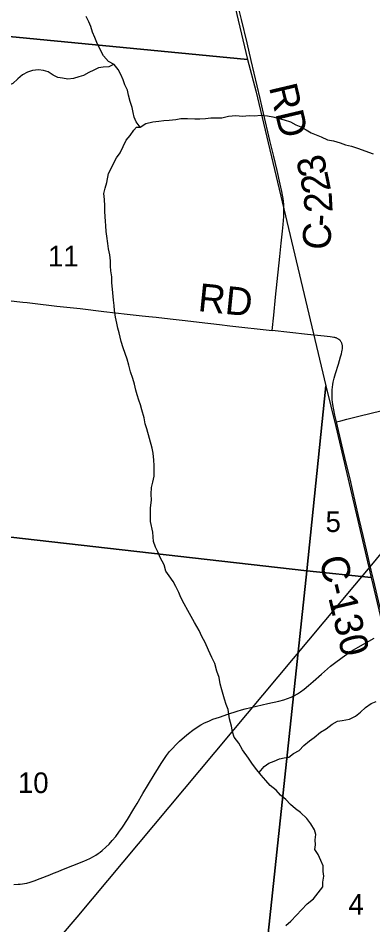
# Model space of a CAD drawing. Extents: x 0 to 1101, y 0 to 440.
# Drawn here: x 843.45 to 844.169, y 371.828 to 373.668 of the extents above; entities that cross this region are included whole.
import ezdxf

# ---------------------------------------------------------------- set-up
doc = ezdxf.new("R2010")
doc.units = 0
for name, color, linetype in [('GM_X_County_Road', 7, 'Continuous'), ('GM_X_County_Road_Text', 7, 'Continuous'), ('GM_X_Minor_River', 7, 'Continuous'), ('GM_X_Rail_Line', 7, 'Continuous'), ('GM_X_Section', 7, 'Continuous'), ('GM_X_Section_Text', 7, 'Continuous'), ('GM_X_Township_Road', 7, 'Continuous'), ('GM_X_Township_Road_Text', 7, 'Continuous')]:
    doc.layers.add(name, color=color, linetype=linetype)

msp = doc.modelspace()

# ---------------------------------------------------------------- linework, layer by layer
at = {"layer": 'GM_X_County_Road'}
for points in [[(843.9652, 373.0339), (843.9682, 373.0647), (843.9719, 373.1013), (843.9752, 373.1334), (843.9802, 373.1841), (843.9832, 373.2113), (843.986, 373.2354), (843.9873, 373.249), (843.9886, 373.2651), (843.9889, 373.2776), (843.9887, 373.2843), (843.9885, 373.2895), (843.9879, 373.2956), (843.9871, 373.3019), (843.9861, 373.3083), (843.9846, 373.316), (843.9815, 373.3306), (843.975, 373.3584), (843.9682, 373.3868), (843.9604, 373.4195), (843.9475, 373.4745), (843.9406, 373.5042), (843.9223, 373.5815), (843.914, 373.6172), (843.9028, 373.6649), (843.891, 373.7144)], [(844.0951, 372.8485), (844.092, 372.8618), (844.0898, 372.8727), (844.0879, 372.8837), (844.0874, 372.8887), (844.0868, 372.8941), (844.0865, 372.9015), (844.0865, 372.9083), (844.0868, 372.9136), (844.0872, 372.9188), (844.088, 372.9243), (844.0889, 372.9291), (844.0907, 372.9369), (844.0933, 372.9465), (844.0992, 372.9655), (844.1037, 372.9804), (844.1053, 372.9864), (844.1062, 372.9906), (844.1068, 372.9938), (844.1072, 372.9964), (844.1073, 372.9985), (844.1074, 373.0003), (844.1073, 373.0021), (844.1072, 373.0036), (844.1071, 373.0048), (844.1068, 373.0059), (844.1064, 373.0072), (844.106, 373.0084), (844.1055, 373.0096), (844.105, 373.0105), (844.1043, 373.0116), (844.1037, 373.0126), (844.103, 373.0133), (844.1021, 373.0142), (844.1003, 373.0158), (844.0992, 373.0165), (844.0981, 373.0172), (844.0969, 373.0179), (844.0957, 373.0184), (844.0944, 373.0188), (844.0932, 373.0192), (844.0917, 373.0195), (844.0901, 373.0199), (844.0866, 373.0205), (844.0826, 373.0211), (844.0766, 373.0219), (844.0705, 373.0226), (844.0364, 373.026), (843.9652, 373.0339)], [(844.0951, 372.8485), (844.1043, 372.8508), (844.1163, 372.8539), (844.1435, 372.8605), (844.1852, 372.8706), (844.2117, 372.877), (844.2969, 372.8975), (844.3435, 372.9084), (844.3956, 372.9205), (844.4379, 372.9305), (844.4724, 372.9384), (844.4991, 372.9444), (844.5323, 372.9523), (844.5711, 372.9613), (844.6182, 372.9725), (844.6593, 372.9823), (844.7029, 372.9924), (844.7146, 372.9951)], [(844.1957, 372.4215), (844.1896, 372.4469), (844.1823, 372.4766), (844.1707, 372.5261), (844.1657, 372.5478), (844.1583, 372.5799), (844.1493, 372.618), (844.1415, 372.6519), (844.1339, 372.6846), (844.1278, 372.7113), (844.1227, 372.733), (844.1148, 372.765), (844.1061, 372.8019), (844.0951, 372.8485)], [(843.4417, 371.9103), (843.4505, 371.9104), (843.4545, 371.9107), (843.4592, 371.9112), (843.4633, 371.9118), (843.4679, 371.9128), (843.4745, 371.9146), (843.4828, 371.9173), (843.4951, 371.9219), (843.5142, 371.9295), (843.5221, 371.9328), (843.5314, 371.9366), (843.5388, 371.9397), (843.5832, 371.9575), (843.5953, 371.9626), (843.6032, 371.9665), (843.6079, 371.9695), (843.6126, 371.9727), (843.6167, 371.9759), (843.6204, 371.9789), (843.6279, 371.9855), (843.6345, 371.9921), (843.6408, 371.9991), (843.648, 372.0077), (843.6544, 372.0162), (843.6615, 372.0264), (843.6716, 372.0421), (843.6845, 372.0633), (843.6911, 372.0746), (843.7031, 372.0949), (843.7256, 372.1328), (843.7346, 372.147), (843.7399, 372.1554), (843.7453, 372.1637), (843.751, 372.1718), (843.7571, 372.1796), (843.7627, 372.1862), (843.7695, 372.1934), (843.7775, 372.2011), (843.7873, 372.2097), (843.7954, 372.2164), (843.8043, 372.2231), (843.8129, 372.2292), (843.8203, 372.2337), (843.8279, 372.2377), (843.8363, 372.2416), (843.8449, 372.2451), (843.8583, 372.2498), (843.8754, 372.2556), (843.8942, 372.2619), (843.9031, 372.2645), (843.9103, 372.2665), (843.9218, 372.2693), (843.9563, 372.2769), (843.9782, 372.2819), (843.9884, 372.2846), (843.9961, 372.2871), (844.0037, 372.2902), (844.0104, 372.2935), (844.0164, 372.2969), (844.0222, 372.3007), (844.0297, 372.3063), (844.0384, 372.3134), (844.0482, 372.322), (844.065, 372.3367), (844.0832, 372.3526), (844.0914, 372.3591), (844.1068, 372.3707), (844.1164, 372.3775), (844.1252, 372.3833), (844.1391, 372.3913), (844.1716, 372.4095)]]:
    msp.add_lwpolyline(points, dxfattribs=at)
at = {"layer": 'GM_X_Minor_River'}
for points in [[(843.6978, 373.4464), (843.6892, 373.4571), (843.6851, 373.4666), (843.6833, 373.4761), (843.6811, 373.4864), (843.6774, 373.4985), (843.6737, 373.5115), (843.6719, 373.5214), (843.6666, 373.532), (843.6629, 373.5423), (843.6581, 373.5534), (843.6532, 373.5633), (843.6446, 373.5732), (843.6336, 373.5794), (843.6234, 373.5909), (843.617, 373.6027), (843.6096, 373.6183), (843.6059, 373.6286), (843.6006, 373.6389), (843.5977, 373.6507), (843.5932, 373.6602), (843.588, 373.6709)], [(843.6435, 373.5738), (843.6339, 373.5688), (843.6228, 373.5681), (843.6133, 373.567), (843.6037, 373.5622), (843.5938, 373.557), (843.5827, 373.5514), (843.5731, 373.5484), (843.5625, 373.5451), (843.5506, 373.5437), (843.54, 373.5457), (843.5305, 373.5469), (843.521, 373.5519), (843.5112, 373.5584), (843.5013, 373.5612), (843.4914, 373.5628), (843.4792, 373.5614), (843.4689, 373.5581), (843.459, 373.5528), (843.4494, 373.5442), (843.4394, 373.5352), (843.4298, 373.5311), (843.4211, 373.5285)], [(843.633, 373.3521), (843.6396, 373.3638), (843.6442, 373.3743), (843.6493, 373.3842), (843.657, 373.3943), (843.6628, 373.4072), (843.669, 373.42), (843.6771, 373.4298), (843.6844, 373.4404), (843.69, 373.4466), (843.6978, 373.4464), (843.7093, 373.4538), (843.7231, 373.4571), (843.7356, 373.4585), (843.7455, 373.4596), (843.7562, 373.4606), (843.7695, 373.462), (843.7802, 373.4638), (843.7932, 373.4637), (843.808, 373.4636), (843.8183, 373.4635), (843.8297, 373.4638), (843.8404, 373.4652), (843.8632, 373.4654), (843.8762, 373.4687), (843.8911, 373.4701), (843.9048, 373.4688), (843.9181, 373.4698), (843.9291, 373.4697), (843.9421, 373.4708), (843.9558, 373.4691), (843.9664, 373.4671), (843.9763, 373.4647), (843.9896, 373.4612), (844.0021, 373.4569), (844.0131, 373.4511), (844.023, 373.4472), (844.0336, 373.4407), (844.0442, 373.4349), (844.0544, 373.431), (844.0643, 373.4271), (844.0772, 373.4206), (844.0893, 373.4189), (844.103, 373.4146), (844.1136, 373.4107), (844.1254, 373.4076), (844.1398, 373.4033), (844.1527, 373.3986), (844.1694, 373.3924)], [(844.0022, 372.0723), (843.9924, 372.0827), (843.9819, 372.0911), (843.9732, 372.1011), (843.9611, 372.1107), (843.9524, 372.1207), (843.943, 372.1318), (843.9336, 372.1425), (843.9253, 372.154), (843.9171, 372.1666), (843.9047, 372.1835), (843.8972, 372.1969), (843.8881, 372.2087), (843.8844, 372.2194), (843.8823, 372.2312), (843.8786, 372.2464), (843.8757, 372.2647), (843.8716, 372.2754), (843.8683, 372.286), (843.8627, 372.3047), (843.8598, 372.3169), (843.8573, 372.3298), (843.8528, 372.3428), (843.8488, 372.3584), (843.8428, 372.3702), (843.8361, 372.3851), (843.8294, 372.4011), (843.8226, 372.4134), (843.817, 372.4256), (843.8077, 372.4416), (843.8005, 372.4534), (843.7942, 372.466), (843.7867, 372.4794), (843.78, 372.492), (843.7759, 372.5023), (843.7699, 372.5145), (843.7646, 372.5244), (843.7564, 372.5359), (843.7496, 372.5458), (843.7463, 372.5584), (843.7381, 372.5736), (843.7336, 372.5847), (843.7287, 372.5946), (843.7243, 372.606), (843.7229, 372.6247), (843.7182, 372.6463), (843.7181, 372.674), (843.7205, 372.69), (843.7198, 372.7017), (843.7203, 372.7154), (843.7231, 372.7264), (843.7259, 372.7381), (843.726, 372.7483), (843.7257, 372.7601), (843.7254, 372.7711), (843.724, 372.7848), (843.7215, 372.7951), (843.7112, 372.8346), (843.7075, 372.8445), (843.7053, 372.8567), (843.7009, 372.873), (843.6979, 372.8829), (843.6946, 372.8928), (843.6916, 372.9035), (843.6887, 372.913), (843.6857, 372.9248), (843.6824, 372.9362), (843.678, 372.9503), (843.6743, 372.9636), (843.6714, 372.9754), (843.6669, 372.9872), (843.6632, 372.999), (843.6591, 373.0115), (843.6551, 373.0294), (843.6525, 373.0389), (843.6503, 373.0488), (843.6474, 373.0609), (843.6456, 373.0742), (843.645, 373.0845), (843.6435, 373.0955), (843.6415, 373.1175), (843.6404, 373.1304), (843.6402, 373.1426), (843.638, 373.1551), (843.6373, 373.1646), (843.6371, 373.1752), (843.636, 373.1877), (843.6335, 373.1995), (843.6321, 373.2105), (843.6299, 373.225), (843.6285, 373.2345), (843.6278, 373.2459), (843.6275, 373.2554), (843.6268, 373.2648), (843.6262, 373.2762), (843.6259, 373.2865), (843.6253, 373.2994), (843.6242, 373.3119), (843.6266, 373.3225), (843.6298, 373.3343), (843.633, 373.3521)], [(843.9385, 372.137), (843.9485, 372.1492), (843.9581, 372.156), (843.9688, 372.16), (843.9795, 372.1649), (843.9894, 372.1671), (843.9989, 372.1685), (844.0085, 372.1756), (844.02, 372.1816), (844.0292, 372.1921), (844.0404, 372.2015), (844.0499, 372.2079), (844.063, 372.2192), (844.0745, 372.2259), (844.0864, 372.2353), (844.0971, 372.2412), (844.107, 372.2427), (844.1215, 372.2452), (844.1337, 372.2515), (844.1441, 372.2594), (844.1544, 372.2692), (844.1655, 372.277), (844.1755, 372.2815)], [(843.9928, 371.8271), (844.0028, 371.8358), (844.0143, 371.8479), (844.0247, 371.8584), (844.0362, 371.8708), (844.0485, 371.8806), (844.0585, 371.893), (844.0677, 371.9055), (844.0674, 371.915), (844.0695, 371.9268), (844.0684, 371.9367), (844.0681, 371.9477), (844.0633, 371.9584), (844.058, 371.9706), (844.0517, 371.9813), (844.0525, 371.9908), (844.0522, 372.0007), (844.0535, 372.0113), (844.0505, 372.0209), (844.043, 372.0331), (844.0351, 372.0438), (844.0227, 372.0558), (844.0121, 372.0638), (844.0022, 372.0723)]]:
    msp.add_lwpolyline(points, dxfattribs=at)
at = {"layer": 'GM_X_Rail_Line'}
msp.add_lwpolyline([(841.4728, 368.6426), (841.5036, 368.6835), (841.5374, 368.7376), (841.6188, 368.8614), (841.6632, 368.9407), (841.7044, 369.0211), (841.7667, 369.1427), (842.0077, 369.6134), (842.282, 370.1444), (842.3817, 370.3472), (842.4321, 370.4445), (842.4792, 370.5194), (842.5317, 370.5965), (842.5789, 370.6613), (842.6287, 370.7304), (842.8514, 370.9969), (843.1012, 371.295), (843.5697, 371.844), (844.1633, 372.5544), (844.2567, 372.6675)], dxfattribs=at)
at = {"layer": 'GM_X_Section'}
for points in [[(843.2377, 374.6786), (843.6631, 374.6284), (843.6929, 374.5119), (843.75, 374.28), (843.9153, 373.5836), (843.1376, 373.6589)], [(843.1376, 373.6589), (843.9153, 373.5836), (843.9316, 373.52), (844.074, 372.9217), (844.0354, 372.5461), (843.0306, 372.6604)], [(844.0939, 372.839), (844.1659, 372.5327), (844.0354, 372.5461), (844.074, 372.9217)], [(843.0306, 372.6604), (844.0354, 372.5461), (843.9352, 371.6074), (842.9284, 371.7073)], [(844.0354, 372.5461), (844.1659, 372.5327), (844.2091, 372.3504), (844.2884, 372.001), (844.3881, 371.5681), (843.9352, 371.6074)]]:
    msp.add_lwpolyline(points, close=True, dxfattribs=at)
at = {"layer": 'GM_X_Township_Road'}
msp.add_lwpolyline([(843.3998, 373.0982), (843.46, 373.0914), (843.4686, 373.0904), (843.4791, 373.0893), (843.5287, 373.0835), (843.5757, 373.0783), (843.6239, 373.0725), (843.6711, 373.0672), (843.7013, 373.0638), (843.7149, 373.0624), (843.7297, 373.0607), (843.7581, 373.0573), (843.7884, 373.0539), (843.8168, 373.0507), (843.8581, 373.0459), (843.8791, 373.0436), (843.9652, 373.0339)], dxfattribs=at)

# ---------------------------------------------------------------- texts
at = {"layer": 'GM_X_County_Road_Text'}
for s, height, rotation, p in [('RD', 0.05682, 283.3255, (843.9582, 373.5277)), ('3', 0.0568, 102.3629, (844.0773, 373.3534)), ('2', 0.0568, 101.6319, (844.0846, 373.3183)), ('2', 0.0568, 92.9622, (844.0876, 373.2741)), ('-', 0.0568, 85.9539, (844.0858, 373.2432)), ('C', 0.0568, 84.6098, (844.0813, 373.1953)), ('C-130', 0.05682, 283.3598, (844.0599, 372.5704))]:
    msp.add_text(s, height=height, rotation=rotation, dxfattribs=at).set_placement(p)
at = {"layer": 'GM_X_Section_Text'}
for s, height, p in [('11', 0.04186, (843.5106, 373.1638)), ('5', 0.0419, (844.0731, 372.6251)), ('10', 0.04186, (843.4497, 372.0955)), ('4', 0.0419, (844.1197, 371.8491))]:
    msp.add_text(s, height=height, rotation=0, dxfattribs=at).set_placement(p)
at = {"layer": 'GM_X_Township_Road_Text'}
msp.add_text('RD', height=0.05682, rotation=354.1407, dxfattribs=at).set_placement((843.8131, 373.0734))

doc.saveas('drawing.dxf')
